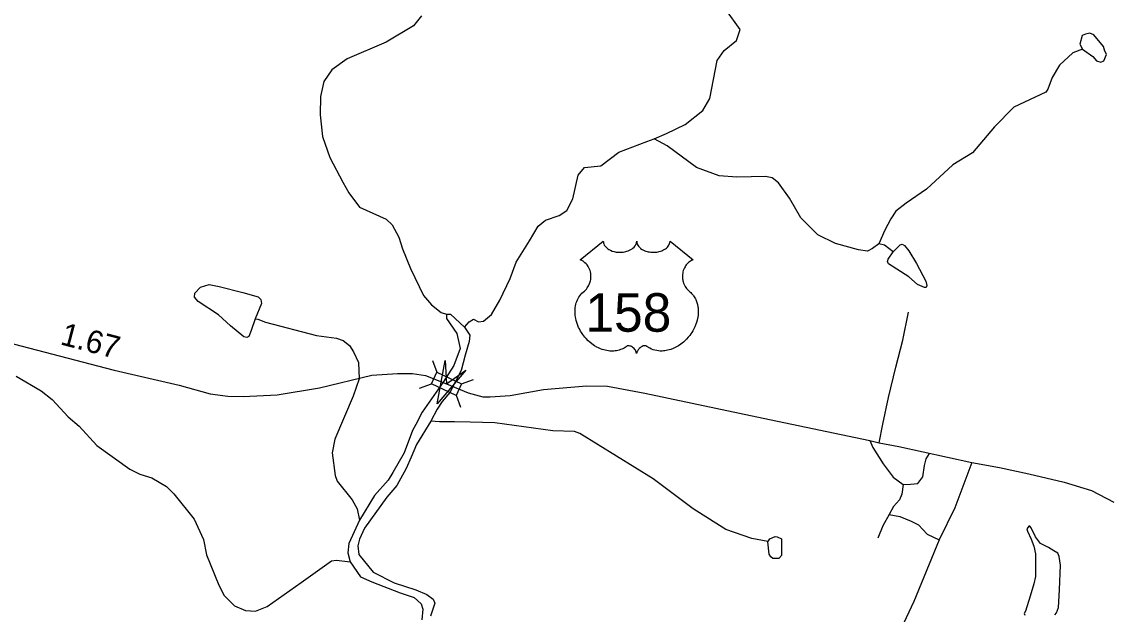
# Model space of a CAD drawing. Extents: x 2056842 to 2160602, y 826753 to 1016856.
# Drawn here: x 2065985 to 2071991, y 939319 to 942585 of the extents above; entities that cross this region are included whole.
import ezdxf

# ---------------------------------------------------------------- set-up
doc = ezdxf.new("R2010")
doc.units = 0
for name, color, linetype in [('Exist Hydrographic Creek Single Shore', 7, 'Continuous'), ('Exist Hydrographic Misc Water Feature', 7, 'Continuous'), ('Exist Hydrographic Pond Under 1500 Sq Ft', 7, 'Continuous'), ('Exist Hydrographic River Shore', 7, 'Continuous'), ('Exist Road Non-System Type 51', 7, 'Continuous'), ('Exist Road Primary US Attributed', 7, 'Continuous'), ('Exist Road Primary US Mileage Hundredths English Label', 7, 'Continuous'), ('Exist Road Primary US Shield CELL', 7, 'Continuous'), ('Exist Road Primary US Shield Number Label', 7, 'Continuous'), ('Exist Road Primary US Structure Standard Bridge CELL', 7, 'Continuous'), ('Exist Road Secondary Structure Standard Bridge Attributed CELL', 7, 'Continuous'), ('Exist Road Secondary Type 51 Attributed', 7, 'Continuous')]:
    doc.layers.add(name, color=color, linetype=linetype)

msp = doc.modelspace()

# ---------------------------------------------------------------- linework, layer by layer
at = {"layer": 'Exist Hydrographic Creek Single Shore'}
for points in [[(2069473.6, 941939.1), (2069542.5, 941968.4), (2069645.4, 942017.7), (2069743.9, 942096), (2069781.6, 942161.2), (2069822.8, 942371.9), (2069861.3, 942426.5), (2069928, 942481.6), (2069949.7, 942543.2), (2069870.3, 942651.8)], [(2068427.8, 940900.7), (2068453.9, 940931.1), (2068478.5, 940945.6), (2068506, 940931.1), (2068532.1, 940934), (2068577, 940970.3), (2068623.3, 941049.7), (2068679.2, 941169.7), (2068713.2, 941258.8), (2068787.1, 941377.6), (2068834.9, 941458.1), (2068874, 941491.4), (2068950.8, 941517.5), (2068992.8, 941543.6), (2069026.2, 941608.9), (2069055.9, 941738.4), (2069089.6, 941781.4), (2069179.5, 941790.1), (2069279.4, 941866.9), (2069433.9, 941925.2), (2069473.6, 941939.1)]]:
    msp.add_lwpolyline(points, dxfattribs=at)
at = {"layer": 'Exist Hydrographic Misc Water Feature'}
for points in [[(2071838.9, 942433.7), (2071784.9, 942413.6), (2071711.1, 942345.6), (2071671.1, 942277.4), (2071647.3, 942213.4), (2071635.3, 942197.3), (2071459.4, 942114.8), (2071351.7, 942004.9), (2071231.9, 941862.6), (2071121.8, 941795.9), (2070976.4, 941662.2), (2070865.4, 941584.9), (2070808.9, 941541.5), (2070779.9, 941499.4), (2070748, 941435.6), (2070714.4, 941360.2)], [(2071838.9, 942433.7), (2071894.8, 942393.8), (2071914.9, 942369.9), (2071938.9, 942361.9), (2071954.9, 942370), (2071970.9, 942404), (2071960.9, 942424)], [(2070714.4, 941360.2), (2070679.6, 941335.6), (2070652.1, 941321.1), (2070601.4, 941328.3), (2070474.9, 941363.3), (2070376.8, 941411), (2070284.6, 941504.8), (2070220.4, 941612.7), (2070160.3, 941696.7), (2070126.3, 941724.7), (2070088.1, 941732.6), (2069930.2, 941728.2), (2069832.3, 941735), (2069707.7, 941781.4), (2069546.9, 941901.7), (2069473.8, 941939.3)], [(2070792.9, 941315.8), (2070746.3, 941353), (2070714.4, 941360.2)], [(2070792.9, 941315.8), (2070832.1, 941355.9), (2070842.2, 941358.8), (2070856.7, 941351.5), (2070879.9, 941322.5), (2070921.9, 941253), (2070974, 941154.4), (2070979.8, 941131.2), (2070975.5, 941119.6), (2070966.8, 941119.6), (2070927.7, 941137), (2070879.9, 941179), (2070768.3, 941250.1), (2070762.5, 941263.1), (2070765.4, 941276.1), (2070792.9, 941315.8)], [(2067273, 940947.2), (2067250.4, 940882.5), (2067238.8, 940849.2), (2067227.2, 940843.4), (2067209.8, 940847.7), (2067137.4, 940908.6), (2067070.8, 940969.5), (2066959.2, 941042), (2066938.9, 941066.7), (2066940.4, 941088.4), (2066970.8, 941121.8), (2067018.6, 941136.3), (2067075.1, 941126.1), (2067205.5, 941092.8), (2067289.5, 941068.1), (2067304, 941053.6), (2067306.9, 941031.9), (2067273, 940947.2)], [(2067273, 940947.2), (2067287.7, 940945.4), (2067329.8, 940929.5), (2067611.9, 940856), (2067722, 940840.2), (2067757.9, 940828.3), (2067794, 940800.3), (2067816.2, 940764.4), (2067842.2, 940706.4), (2067846.3, 940616.5), (2067814.5, 940520.4), (2067713, 940284.2), (2067697, 940208.2), (2067713.4, 940084.1), (2067725.5, 940052.2), (2067807.4, 939949.6), (2067836.3, 939898.9), (2067847.9, 939838)], [(2065954.5, 940630.9), (2066092.7, 940551.1), (2066152.6, 940503.3), (2066240.7, 940407.5), (2066301, 940355.5), (2066399, 940249.7), (2066581.3, 940118.1), (2066637.3, 940090.2), (2066703.5, 940070.3), (2066783.5, 940022.5), (2066823.5, 939982.5), (2066935.9, 939842.7), (2066988.2, 939730.8), (2067004.2, 939646.9), (2067072.4, 939479), (2067101.2, 939422.6), (2067159.1, 939364.6), (2067220, 939338.6), (2067275, 939335.7), (2067338.8, 939361.7), (2067527.2, 939493.7), (2067694.2, 939612.2), (2067722.2, 939616.2), (2067796.3, 939608.3)], [(2070101.9, 939718.6), (2070013.9, 939736.5), (2069869.8, 939786.2), (2069689.5, 939899.8), (2069469.3, 940065.5), (2069064.9, 940314.7), (2069034.8, 940326.6), (2068914.8, 940330.4), (2068594.7, 940373.8), (2068458.8, 940377.6), (2068373.3, 940380.2), (2068290.9, 940379.2), (2068241.5, 940383.1)], [(2071685.1, 939316.1), (2071695.3, 939326.2), (2071705.4, 939355.2), (2071711.2, 939452.4), (2071717, 939588.6), (2071709.8, 939636.5), (2071701.1, 939655.3), (2071680.8, 939668.4), (2071650.4, 939685.8), (2071606.9, 939709), (2071577.9, 939745.2), (2071554.7, 939794.5), (2071547.5, 939803.2), (2071541.7, 939803.2), (2071537.4, 939798.8), (2071531.6, 939788.7), (2071534.5, 939777.1), (2071554.7, 939732.2), (2071569.2, 939694.5), (2071577.9, 939651), (2071577.9, 939577), (2071579.4, 939526.3), (2071569.2, 939485.7), (2071549, 939419), (2071522.9, 939334.9), (2071517.1, 939321.9), (2071520, 939313.2)]]:
    msp.add_lwpolyline(points, dxfattribs=at)
at = {"layer": 'Exist Hydrographic Pond Under 1500 Sq Ft'}
for points in [[(2071854.4, 942517.4), (2071836.5, 942509.6), (2071822.7, 942461.7), (2071838.5, 942433.4)], [(2071960.7, 942423.7), (2071954.7, 942447.8), (2071900.6, 942513.5), (2071878.4, 942521.5), (2071854.4, 942517.4)], [(2070101.8, 939718.3), (2070113.6, 939734.5), (2070141.8, 939746.4), (2070153.9, 939744.5)], [(2070153.9, 939744.5), (2070177.6, 939734.5), (2070178, 939642.6), (2070161.9, 939626.5), (2070145.8, 939626.5)], [(2070145.8, 939626.5), (2070129.8, 939626.5), (2070117.8, 939634.6), (2070109.9, 939650.5), (2070101.8, 939718.3)]]:
    msp.add_lwpolyline(points, dxfattribs=at)
at = {"layer": 'Exist Hydrographic River Shore'}
for points in [[(2068189.9, 942617.9), (2068146.4, 942562.8), (2067995.7, 942472.9), (2067781, 942380.1), (2067695.8, 942319.2), (2067650.9, 942255.4), (2067633.5, 942172.8), (2067630.6, 942072.8), (2067643.8, 941951.8), (2067684, 941835.8), (2067756.4, 941700.1), (2067789.7, 941641.5), (2067849.1, 941563.2), (2067996.6, 941496.5), (2068028.8, 941464.7), (2068064.8, 941396.7), (2068086.7, 941332.6), (2068130.2, 941223.9), (2068201.2, 941076.1), (2068245.4, 941025.1), (2068299.6, 940982.9), (2068327.7, 940973.2)], [(2068327.8, 940973.3), (2068327.8, 940949.4), (2068385.8, 940865.9), (2068404.6, 940783.2), (2068369.8, 940690.4), (2068310.3, 940597.3), (2068194.7, 940433), (2068158.8, 940365), (2068140.9, 940332.4), (2068094.2, 940209.1), (2068033.3, 940100.7), (2068007.3, 940056.8), (2067931.6, 939972.6), (2067847.9, 939838)], [(2068327.7, 940973.2), (2068351.6, 940973.3), (2068427.8, 940900.7)], [(2068427.8, 940900.7), (2068457.8, 940857.3), (2068453.8, 940821.3), (2068430.7, 940747), (2068410.1, 940661.4), (2068346.3, 940541.3), (2068304.5, 940491), (2068277.7, 940448.3), (2068241.5, 940383.1)], [(2068241.5, 940383.1), (2068162.3, 940254.1), (2068133.4, 940184.5), (2068105.8, 940122.1), (2068055.1, 940027.9), (2068000.1, 939964.1), (2067875.6, 939792.4), (2067847.8, 939732.2), (2067839.8, 939696.3), (2067844.1, 939648.3), (2067924.1, 939550.2), (2068040.1, 939492.2), (2068160.3, 939453.1), (2068219.7, 939427), (2068254.5, 939400.9), (2068264.4, 939379.1), (2068240.6, 939307)], [(2067847.9, 939838), (2067790.1, 939708.4), (2067784.2, 939656.3), (2067796.3, 939608.3)], [(2067796.3, 939608.3), (2067854.3, 939524.4), (2067916.9, 939496.6), (2068073.4, 939437.1), (2068150.2, 939411), (2068188.5, 939375.1), (2068198.8, 939347.1), (2068192.8, 939287.1)]]:
    msp.add_lwpolyline(points, dxfattribs=at)
at = {"layer": 'Exist Road Non-System Type 51'}
for points in [[(2070716.3, 940262.7), (2070735.5, 940367), (2070766.7, 940514), (2070807.5, 940681.5), (2070846, 940830), (2070877.3, 940983.6)], [(2070664.2, 940276.2), (2070681.1, 940238), (2070738.7, 940148.4), (2070793.1, 940074.8), (2070849, 940033.2)], [(2070849, 940033.2), (2070889, 940036.4), (2070929, 940039.6), (2070957.8, 940076.4), (2070965.8, 940138.8), (2070975.4, 940175.6), (2070994.5, 940205.5)], [(2070849, 940033.2), (2070841.1, 939980.4), (2070828.3, 939948.4), (2070794.7, 939911.6), (2070770.7, 939868.4)], [(2070770.7, 939868.4), (2070737.1, 939806), (2070708.3, 939738.8)], [(2070770.7, 939868.4), (2070829.9, 939857.2), (2070892.2, 939831.6), (2070933.8, 939810.8), (2070980.2, 939759.6), (2071047.4, 939729.2)]]:
    msp.add_lwpolyline(points, dxfattribs=at)
at = {"layer": 'Exist Road Primary US Attributed'}
for points in [[(2065809.5, 940842.8), (2066494.6, 940663.7), (2066853.9, 940580.7), (2067025, 940534.3), (2067122.5, 940519.9), (2067207.3, 940518.3), (2067394.6, 940528.3), (2067628.1, 940566.7), (2067915.9, 940637.1), (2068058.7, 940645.2), (2068140.9, 940645.2), (2068213.6, 940634.4), (2068329.3, 940588.6)], [(2068329.3, 940588.6), (2068448.4, 940539.5), (2068528.4, 940517.1), (2068568.9, 940517), (2068679.2, 940525), (2068863.1, 940557), (2069101.4, 940577.8), (2069216.5, 940576.2), (2069422.8, 940537.8), (2070075.8, 940400.3), (2070664.2, 940276.2), (2070716.3, 940262.7), (2070824.8, 940242.4), (2071227.2, 940155.1)], [(2071227.2, 940155.1), (2071380, 940126.6), (2071542.3, 940092.2), (2071736.2, 940046.2), (2071888.1, 939999.8), (2072010.4, 939936.6)]]:
    msp.add_lwpolyline(points, dxfattribs=at)
at = {"layer": 'Exist Road Primary US Shield CELL'}
msp.add_lwpolyline([(2069193.9, 941375.4), (2069194.3, 941370), (2069195.6, 941363.7), (2069196.6, 941360.5), (2069199.5, 941354.2), (2069204.4, 941346.9), (2069211.2, 941339.7), (2069218.8, 941333.3), (2069224, 941330), (2069232.8, 941325.3), (2069242.7, 941321.1), (2069253.8, 941317.9), (2069265.1, 941315.6), (2069277.5, 941314.3), (2069289.7, 941314), (2069303, 941315), (2069317.5, 941317.8), (2069324.3, 941319.6), (2069331.8, 941322.2), (2069338.8, 941325.1), (2069346.5, 941329.2), (2069352.6, 941333.1), (2069357.4, 941336.6), (2069364.3, 941343.1), (2069369.7, 941349.9), (2069372, 941353.7), (2069374, 941357.4), (2069376.7, 941365.1), (2069377.4, 941368.5), (2069378, 941375.6), (2069378.4, 941369.7), (2069379, 941365.9), (2069380, 941362.3), (2069381.5, 941358.4), (2069384.3, 941353), (2069387.3, 941348.4), (2069393, 941341.6), (2069396.6, 941338.3), (2069399.9, 941335.6), (2069408.6, 941329.6), (2069418.8, 941324.5), (2069423.8, 941322.3), (2069429, 941320.4), (2069435.5, 941318.5), (2069442.3, 941316.9), (2069449, 941315.7), (2069455.8, 941314.7), (2069462.8, 941314.2), (2069468.5, 941314), (2069475.5, 941314.1), (2069481.9, 941314.5), (2069488.5, 941315.3), (2069495.8, 941316.5), (2069501.7, 941317.8), (2069509.4, 941319.8), (2069516.4, 941322.3), (2069522.6, 941325), (2069530.5, 941329.2), (2069537, 941333.2), (2069541.7, 941337), (2069547.3, 941342.2), (2069552.6, 941348.3), (2069555.8, 941352.8), (2069558, 941357.4), (2069560, 941362.3), (2069561.3, 941367.5), (2069561.9, 941371.9), (2069562, 941375.8), (2069690.6, 941273.3), (2069687.6, 941272.2), (2069680.6, 941268.8), (2069675, 941265.5), (2069666.2, 941259.3), (2069662.4, 941255.8), (2069658.6, 941252.3), (2069655.1, 941248.5), (2069652, 941244.9), (2069648.3, 941239.7), (2069645, 941234.6), (2069641.7, 941228.9), (2069639.3, 941223.9), (2069635.3, 941213.6), (2069633.4, 941207.1), (2069632.2, 941201.5), (2069630.7, 941190), (2069630.3, 941184.6), (2069630.3, 941179.2), (2069630.6, 941173.5), (2069631.2, 941168), (2069632.2, 941162.3), (2069633.1, 941157.3), (2069634.7, 941151.1), (2069636.9, 941144), (2069639.7, 941137.1), (2069645.6, 941125.9), (2069653.2, 941114.5), (2069658.6, 941108.1), (2069663.9, 941102.6), (2069671.8, 941096), (2069676.1, 941092.2), (2069681.1, 941087.2), (2069689.1, 941077.9), (2069692.4, 941073.5), (2069695.7, 941068.5), (2069698.7, 941063.4), (2069701.8, 941058), (2069704.2, 941053.2), (2069708.7, 941042.2), (2069712, 941031.4), (2069713.5, 941025.8), (2069715.9, 941013.2), (2069716.8, 941007), (2069717.8, 940994.7), (2069717.9, 940979.8), (2069716.7, 940965.6), (2069714.1, 940949.2), (2069711.9, 940939.3), (2069708.5, 940927.8), (2069705.2, 940917.8), (2069699.3, 940903.2), (2069694.1, 940892.5), (2069687.4, 940880.1), (2069682.7, 940872.6), (2069677.3, 940864.5), (2069670.6, 940855.2), (2069662.7, 940845.4), (2069653.2, 940834.9), (2069645.5, 940827.3), (2069635.5, 940818.3), (2069629.4, 940813.3), (2069620.8, 940806.8), (2069608.9, 940798.9), (2069597.2, 940792.1), (2069587.3, 940787), (2069578.5, 940783.2), (2069567.1, 940778.9), (2069548.1, 940773.6), (2069541.2, 940772.2), (2069533, 940771), (2069525.3, 940770.2), (2069517.9, 940769.7), (2069507.8, 940769.7), (2069497.9, 940770.5), (2069488.5, 940771.9), (2069478.7, 940773.9), (2069468.4, 940777), (2069459.1, 940780.6), (2069449.7, 940785.3), (2069433.8, 940795.3), (2069429.2, 940797.7), (2069426.6, 940798.4), (2069420.4, 940798.7), (2069414.7, 940797.5), (2069408.8, 940795.1), (2069405.2, 940793.2), (2069400.4, 940790.1), (2069396.8, 940787.2), (2069392.4, 940783), (2069389.3, 940779.6), (2069387, 940776.8), (2069382.6, 940769.7), (2069381, 940766.4), (2069379.3, 940762.1), (2069377.8, 940755.7), (2069375.8, 940763.7), (2069373.4, 940769.1), (2069370.7, 940773.6), (2069367.9, 940777.7), (2069363.4, 940782.8), (2069359.3, 940786.7), (2069354.5, 940790.6), (2069349.3, 940793.8), (2069345.2, 940795.9), (2069341.4, 940797.3), (2069336.8, 940798.5), (2069333, 940798.8), (2069329.8, 940798.7), (2069325.6, 940797.7), (2069319.7, 940793.5), (2069314.2, 940789.7), (2069308.2, 940786), (2069301.1, 940782.2), (2069295.9, 940779.8), (2069289.6, 940777.3), (2069282.3, 940774.9), (2069274.4, 940772.9), (2069266.3, 940771.3), (2069259.2, 940770.1), (2069251.5, 940769.4), (2069244.6, 940769.2), (2069237.4, 940769.3), (2069230.6, 940769.8), (2069222.8, 940770.5), (2069213.1, 940772), (2069205, 940773.8), (2069196.5, 940776.1), (2069187.8, 940778.8), (2069178.4, 940782.4), (2069166.7, 940787.5), (2069158.6, 940791.6), (2069145.8, 940799), (2069130.7, 940809.4), (2069119.4, 940818.6), (2069111.1, 940826.1), (2069098.9, 940838.6), (2069091.7, 940846.7), (2069080.4, 940861.3), (2069073.2, 940871.9), (2069068.5, 940879.6), (2069061.7, 940892.1), (2069057.9, 940899.9), (2069053.1, 940911.3), (2069049.2, 940921.7), (2069046, 940931.6), (2069044.3, 940937.9), (2069041.9, 940948.9), (2069040.4, 940956.7), (2069039, 940967.5), (2069038.2, 940978.8), (2069038, 940989.2), (2069038.3, 940997.9), (2069039.3, 941008), (2069041, 941018.7), (2069043, 941027.9), (2069044.9, 941034.5), (2069047.6, 941042.5), (2069051.2, 941051.4), (2069055.5, 941059.9), (2069059.6, 941067), (2069064.6, 941074.6), (2069069.7, 941081.1), (2069076.2, 941088.2), (2069083.1, 941094.7), (2069089.3, 941099.8), (2069096.8, 941107.1), (2069100.6, 941111.5), (2069105.3, 941117.7), (2069109, 941123.4), (2069112, 941128.5), (2069115.9, 941136), (2069118.3, 941141.6), (2069121.2, 941150.3), (2069122.7, 941156.4), (2069124.2, 941164.2), (2069125.2, 941171.6), (2069125.6, 941180.8), (2069125.4, 941188.4), (2069124.4, 941197.2), (2069122.7, 941205.8), (2069120.7, 941213.2), (2069117.5, 941221.7), (2069114.6, 941227.9), (2069109.6, 941236.4), (2069104.2, 941244.2), (2069098.5, 941250.6), (2069092.8, 941256.3), (2069087.4, 941260.5), (2069082.1, 941264.3), (2069075.6, 941268.2), (2069069.3, 941271.3), (2069065.3, 941272.9)], close=True, dxfattribs=at)
at = {"layer": 'Exist Road Primary US Structure Standard Bridge CELL'}
for p, q in [((2068251.6, 940717.4), (2068275.2, 940652.6)), ((2068180.4, 940565.1), (2068245.3, 940588.6)), ((2068411.9, 940588.3), (2068476.8, 940611.9)), ((2068382.7, 940525.8), (2068406.3, 940461))]:
    msp.add_line(p, q, dxfattribs=at)
msp.add_lwpolyline([(2068275.2, 940652.6), (2068412.1, 940588.6), (2068382.2, 940524.7), (2068245.3, 940588.6)], close=True, dxfattribs=at)
at = {"layer": 'Exist Road Secondary Structure Standard Bridge Attributed CELL'}
msp.add_lwpolyline([(2068435, 940664.2), (2068277.1, 940478.5), (2068321, 940718.3), (2068329.3, 940588.6)], close=True, dxfattribs=at)
at = {"layer": 'Exist Road Secondary Type 51 Attributed'}
msp.add_lwpolyline([(2071227.2, 940155.1), (2071133.4, 939905.5), (2071047.4, 939729.2), (2070907.8, 939388.2), (2070807.5, 939176.5)], dxfattribs=at)

# ---------------------------------------------------------------- texts
at = {"layer": 'Exist Road Primary US Mileage Hundredths English Label'}
msp.add_text('1.67', height=125, rotation=345.34535, dxfattribs=at).set_placement((2066192.1, 940807.3))
at = {"layer": 'Exist Road Primary US Shield Number Label'}
msp.add_text('158', height=212.5, dxfattribs=at).set_placement((2069095.1, 940876.1))

doc.saveas('drawing.dxf')
